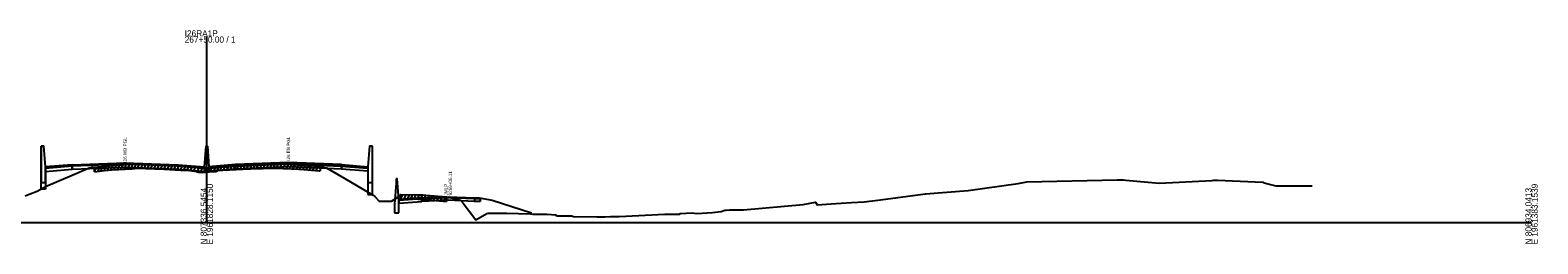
# Model space of a CAD drawing. Extents: x 1017 to 19997, y -1947 to 50737.
# Drawn here: x 10520 to 11203, y 17490 to 17587 of the extents above; entities that cross this region are included whole.
import ezdxf

# ---------------------------------------------------------------- set-up
doc = ezdxf.new("R2010")
doc.units = 0
for name, color, linetype in [('RD_GPK_XS_Cell', 7, 'Continuous'), ('RD_XS_Base', 7, 'Continuous'), ('RD_XS_ExGround', 7, 'Continuous'), ('RD_XS_ExPaveRet', 7, 'Continuous'), ('RD_XS_Greenside', 7, 'Continuous'), ('RD_XS_MedBWall', 7, 'Continuous'), ('RD_XS_Pave', 7, 'Continuous'), ('RD_XS_PaveOvlay', 7, 'Continuous'), ('RD_XS_TX_Notes', 7, 'Continuous')]:
    doc.layers.add(name, color=color, linetype=linetype)

msp = doc.modelspace()

# ---------------------------------------------------------------- linework, layer by layer
at = {"layer": 'RD_GPK_XS_Cell'}
for p, q in [((10600, 17500), (10600, 17584.1)), ((10000, 17500), (10600, 17500)), ((10600, 17500), (11200, 17500))]:
    msp.add_line(p, q, dxfattribs=at)
at = {"layer": 'RD_XS_Base'}
for points in [[(10539, 17525.36), (10527, 17524.4)], [(10527, 17524.4), (10527, 17523.06)], [(10527, 17523.06), (10539, 17524.02)], [(10539, 17524.02), (10539, 17525.36)], [(10539.05, 17524.03), (10539, 17524.02)], [(10539.05, 17525.37), (10539.05, 17524.03)], [(10539.05, 17524.03), (10563, 17525), (10587, 17524.03)], [(10587, 17524.03), (10587, 17525.37)], [(10599, 17524.43), (10587, 17525.37)], [(10587, 17524.03), (10599, 17523.09)], [(10599, 17523.09), (10599, 17524.43)], [(10601, 17523.18), (10601, 17524.52)], [(10613, 17524.12), (10601, 17523.18)], [(10613, 17524.12), (10613, 17525.46)], [(10660.95, 17524.12), (10637, 17525.09), (10613, 17524.12)], [(10660.95, 17524.12), (10660.95, 17525.46)], [(10661, 17524.12), (10660.95, 17524.12)], [(10661, 17525.46), (10661, 17524.12)], [(10661, 17525.45), (10673, 17524.49)], [(10661, 17524.11), (10661, 17525.45)], [(10673, 17523.15), (10661, 17524.11)], [(10673, 17524.49), (10673, 17523.15)], [(10697.32, 17510.84), (10687, 17510.02)], [(10687, 17510.02), (10687, 17508.68)], [(10687, 17508.68), (10697.32, 17509.51)], [(10697.32, 17510.84), (10709.32, 17511.31), (10721.32, 17510.83)], [(10697.32, 17509.51), (10697.32, 17510.84)], [(10721.32, 17509.52), (10709.32, 17509.98), (10697.32, 17509.51)], [(10721.32, 17510.83), (10721.32, 17509.52)], [(10721.32, 17510.83), (10723.32, 17510.75), (10723.82, 17510.73)], [(10723.82, 17509.4), (10721.32, 17509.52)], [(10723.82, 17510.73), (10723.82, 17509.4)]]:
    msp.add_lwpolyline(points, dxfattribs=at)
at = {"layer": 'RD_XS_ExGround'}
msp.add_lwpolyline([(10517.81, 17511.94), (10520.06, 17512.95), (10523.24, 17514.1), (10526.99, 17516.2), (10539.06, 17521.37), (10546.8, 17524.7), (10547.83, 17525.02), (10548.13, 17525.06), (10548.68, 17525.04), (10549.08, 17524.92), (10553.65, 17525.43), (10557.05, 17525.77), (10566.08, 17526.3), (10568.86, 17526.48), (10572.21, 17526.35), (10580.7, 17526.05), (10588.25, 17525.68), (10592.24, 17525.52), (10594.48, 17525.24), (10595.09, 17525.17), (10595.48, 17524.82), (10596.08, 17524.75), (10598.28, 17524.53), (10600.26, 17524.72), (10601.13, 17524.81), (10604.1, 17525.01), (10604.34, 17525.16), (10604.72, 17525.19), (10605, 17525.41), (10607.19, 17525.64), (10619.36, 17526.28), (10620.02, 17526.29), (10631.3, 17526.5), (10641.68, 17526.03), (10643.92, 17525.93), (10650.9, 17525.36), (10651.41, 17525.32), (10652.9, 17525.02), (10654.24, 17524.73), (10660.76, 17520.91), (10675.34, 17512.36), (10676.09, 17511.65), (10678.02, 17509.56), (10679.34, 17509.56), (10680.78, 17509.56), (10682.12, 17509.56), (10683.59, 17509.56), (10686.48, 17511.34), (10687.83, 17512.6), (10695.73, 17512.45), (10697.83, 17512.47), (10699.18, 17512.31), (10708.52, 17511.5), (10713.82, 17510.36), (10714.98, 17510.01), (10716.1, 17508.65), (10721.83, 17501.2), (10726.78, 17504.02), (10727.42, 17504.19), (10735.77, 17504.15), (10746.65, 17503.84), (10747.69, 17503.65), (10753.95, 17503.66), (10758.01, 17503.41), (10758.11, 17503.17), (10758.7, 17502.98), (10765.18, 17502.9), (10766.14, 17502.64), (10776.72, 17502.46), (10780.3, 17502.58), (10782.8, 17502.71), (10786.81, 17502.62), (10807.43, 17503.7), (10814.27, 17503.74), (10814.37, 17503.97), (10814.42, 17503.97), (10819.84, 17504.37), (10821.79, 17504.07), (10829.1, 17504.5), (10832.9, 17504.98), (10834.55, 17505.51), (10835.41, 17505.5), (10836.76, 17505.61), (10843.02, 17505.74), (10870.03, 17508.07), (10875.68, 17509.08), (10876.37, 17507.88), (10882.78, 17508.43), (10887.24, 17508.64), (10892.06, 17509.04), (10897.66, 17509.3), (10903.94, 17509.98), (10925.51, 17512.93), (10944.83, 17514.46), (10967.52, 17517.66), (10971.46, 17518.33), (11012.24, 17519.32), (11013.93, 17519.28), (11014.35, 17519.29), (11015.21, 17519.25), (11016.28, 17519.14), (11031.34, 17517.78), (11055.35, 17519.01), (11055.93, 17519.05), (11056.97, 17519.08), (11057.72, 17519.03), (11078.31, 17518.13), (11078.72, 17517.94), (11084.12, 17516.57), (11090.8, 17516.57), (11096.66, 17516.57), (11100.65, 17516.57)], dxfattribs=at)
at = {"layer": 'RD_XS_ExPaveRet'}
for p, q in [((10549.08, 17522.92), (10550.14, 17525.03)), ((10549.08, 17522.92), (10549.08, 17524.92)), ((10549.08, 17522.92), (10553.65, 17523.43)), ((10550.58, 17523.08), (10551.64, 17525.2)), ((10552.08, 17523.25), (10553.14, 17525.37)), ((10553.58, 17523.42), (10554.63, 17525.53)), ((10553.65, 17523.43), (10557.05, 17523.77)), ((10555.08, 17523.57), (10556.13, 17525.68)), ((10556.58, 17523.72), (10557.62, 17525.8)), ((10557.05, 17523.77), (10566.08, 17524.3)), ((10558.08, 17523.83), (10559.11, 17525.89)), ((10559.58, 17523.92), (10560.61, 17525.98)), ((10561.08, 17524), (10562.11, 17526.06)), ((10562.58, 17524.09), (10563.61, 17526.15)), ((10564.08, 17524.18), (10565.11, 17526.24)), ((10565.58, 17524.27), (10566.61, 17526.33)), ((10566.08, 17524.3), (10568.86, 17524.48)), ((10567.08, 17524.36), (10568.11, 17526.43)), ((10568.58, 17524.46), (10569.57, 17526.45)), ((10568.86, 17524.48), (10572.21, 17524.35)), ((10570.08, 17524.43), (10571.06, 17526.39)), ((10571.58, 17524.37), (10572.56, 17526.34)), ((10572.21, 17524.35), (10580.7, 17524.05)), ((10573.08, 17524.32), (10574.06, 17526.28)), ((10574.58, 17524.27), (10575.56, 17526.23)), ((10576.08, 17524.21), (10577.06, 17526.18)), ((10577.58, 17524.16), (10578.56, 17526.12)), ((10579.08, 17524.11), (10580.06, 17526.07)), ((10580.58, 17524.05), (10581.55, 17526.01)), ((10580.7, 17524.05), (10588.25, 17523.68)), ((10582.08, 17523.98), (10583.05, 17525.94)), ((10583.58, 17523.91), (10584.55, 17525.86)), ((10585.08, 17523.84), (10586.05, 17525.79)), ((10586.58, 17523.77), (10587.55, 17525.72)), ((10588.08, 17523.69), (10589.06, 17525.65)), ((10588.25, 17523.68), (10592.24, 17523.52)), ((10589.58, 17523.63), (10590.56, 17525.59)), ((10591.08, 17523.57), (10592.06, 17525.53)), ((10592.24, 17523.52), (10594.48, 17523.24)), ((10592.58, 17523.48), (10593.52, 17525.36)), ((10594.08, 17523.29), (10595.02, 17525.18)), ((10594.48, 17523.24), (10595.09, 17523.17)), ((10595.09, 17523.17), (10595.48, 17522.82)), ((10595.48, 17522.82), (10596.08, 17522.75)), ((10595.58, 17522.8), (10596.53, 17524.7)), ((10596.08, 17522.75), (10598.28, 17522.53)), ((10597.08, 17522.65), (10598.03, 17524.55)), ((10598.28, 17522.53), (10600.26, 17522.72)), ((10598.58, 17522.56), (10599.63, 17524.66)), ((10600.08, 17522.71), (10601.13, 17524.81)), ((10600.26, 17522.72), (10601.13, 17522.81)), ((10601.13, 17522.81), (10604.1, 17523.01)), ((10601.58, 17522.84), (10602.61, 17524.91)), ((10603.08, 17522.94), (10604.12, 17525.02)), ((10604.1, 17523.01), (10604.34, 17523.16)), ((10604.34, 17523.16), (10604.72, 17523.19)), ((10604.58, 17523.18), (10605.73, 17525.49)), ((10604.72, 17523.19), (10605, 17523.41)), ((10605, 17523.41), (10607.19, 17523.64)), ((10606.08, 17523.52), (10607.13, 17525.63)), ((10607.19, 17523.64), (10619.36, 17524.28)), ((10607.58, 17523.66), (10608.6, 17525.71)), ((10609.08, 17523.74), (10610.1, 17525.79)), ((10610.58, 17523.82), (10611.6, 17525.87)), ((10612.08, 17523.9), (10613.1, 17525.95)), ((10613.58, 17523.98), (10614.6, 17526.03)), ((10615.08, 17524.05), (10616.1, 17526.11)), ((10616.58, 17524.13), (10617.6, 17526.19)), ((10618.08, 17524.21), (10619.1, 17526.27)), ((10619.36, 17524.28), (10620.02, 17524.29)), ((10619.58, 17524.28), (10620.59, 17526.3)), ((10620.02, 17524.29), (10631.3, 17524.5)), ((10621.08, 17524.31), (10622.09, 17526.33)), ((10622.58, 17524.34), (10623.59, 17526.36)), ((10624.08, 17524.37), (10625.09, 17526.39)), ((10625.58, 17524.4), (10626.59, 17526.42)), ((10627.08, 17524.43), (10628.09, 17526.44)), ((10628.58, 17524.45), (10629.59, 17526.47)), ((10630.08, 17524.48), (10631.09, 17526.5)), ((10631.3, 17524.5), (10641.68, 17524.03)), ((10631.58, 17524.49), (10632.55, 17526.45)), ((10633.08, 17524.42), (10634.05, 17526.38)), ((10634.58, 17524.36), (10635.55, 17526.31)), ((10636.08, 17524.29), (10637.05, 17526.24)), ((10637.58, 17524.22), (10638.55, 17526.17)), ((10639.08, 17524.15), (10640.05, 17526.11)), ((10640.58, 17524.08), (10641.55, 17526.04)), ((10641.68, 17524.03), (10643.92, 17523.93)), ((10642.08, 17524.01), (10643.05, 17525.97)), ((10643.58, 17523.94), (10644.54, 17525.88)), ((10643.92, 17523.93), (10650.9, 17523.36)), ((10645.08, 17523.83), (10646.04, 17525.76)), ((10646.58, 17523.71), (10647.54, 17525.63)), ((10648.08, 17523.59), (10649.04, 17525.51)), ((10649.58, 17523.47), (10650.54, 17525.39)), ((10650.9, 17523.36), (10651.41, 17523.32)), ((10651.41, 17525.32), (10651.41, 17523.32)), ((10687.83, 17510.6), (10687.83, 17512.6)), ((10687.83, 17510.6), (10688.82, 17512.58)), ((10687.83, 17510.6), (10695.73, 17510.45)), ((10689.33, 17510.57), (10690.32, 17512.55)), ((10690.83, 17510.54), (10691.82, 17512.52)), ((10692.33, 17510.51), (10693.32, 17512.5)), ((10693.83, 17510.49), (10694.82, 17512.47)), ((10695.33, 17510.46), (10696.33, 17512.46)), ((10695.73, 17510.45), (10697.83, 17510.47)), ((10696.83, 17510.46), (10697.84, 17512.47)), ((10697.83, 17510.47), (10699.18, 17510.31)), ((10698.33, 17510.41), (10699.28, 17512.31)), ((10699.18, 17510.31), (10708.52, 17509.5)), ((10699.83, 17510.26), (10700.79, 17512.18)), ((10701.33, 17510.13), (10702.29, 17512.05)), ((10702.83, 17510), (10703.79, 17511.92)), ((10704.33, 17509.87), (10705.29, 17511.79)), ((10705.83, 17509.74), (10706.79, 17511.65)), ((10707.33, 17509.61), (10708.29, 17511.52)), ((10708.52, 17511.5), (10708.52, 17509.5))]:
    msp.add_line(p, q, dxfattribs=at)
at = {"layer": 'RD_XS_Greenside'}
for points in [[(10723.32, 17511.07), (10729.32, 17510.11)], [(10729.32, 17510.11), (10747.06, 17504.26)]]:
    msp.add_lwpolyline(points, dxfattribs=at)
at = {"layer": 'RD_XS_MedBWall'}
for points in [[(10527, 17525.08), (10526.25, 17534.42), (10525, 17534.42)], [(10525, 17534.42), (10525, 17518)], [(10525, 17515.09), (10525, 17534.42)], [(10599, 17525.08), (10599.75, 17534.51), (10600.25, 17534.51), (10601, 17525.17)], [(10675, 17534.51), (10673.75, 17534.51), (10673, 17525.17)], [(10675, 17518), (10675, 17534.51)], [(10675, 17512.56), (10675, 17534.51)], [(10527, 17518), (10527, 17525.08)], [(10527, 17525.08), (10527, 17515.09)], [(10599, 17523.08), (10599, 17525.08)], [(10601, 17523.08), (10599, 17523.08)], [(10601, 17525.17), (10601, 17523.08)], [(10673, 17525.17), (10673, 17518)], [(10673, 17525.17), (10673, 17512.56)], [(10525, 17518), (10527, 17518)], [(10527, 17515.09), (10525, 17515.09)], [(10673, 17518), (10675, 17518)], [(10685.75, 17517.67), (10685, 17508.33)], [(10687, 17510.33), (10686.25, 17519.67), (10685.75, 17519.67)], [(10685.75, 17519.67), (10685.75, 17517.67)], [(10673, 17512.56), (10675, 17512.56)], [(10685, 17508.33), (10685, 17504.33)], [(10687, 17504.33), (10687, 17510.33)], [(10685, 17504.33), (10687, 17504.33)]]:
    msp.add_lwpolyline(points, dxfattribs=at)
at = {"layer": 'RD_XS_Pave'}
for points in [[(10539, 17525.7), (10527, 17524.74)], [(10527, 17524.74), (10527, 17524.4)], [(10539, 17525.36), (10539, 17525.7)], [(10539.05, 17525.37), (10539, 17525.36)], [(10539.05, 17525.71), (10563, 17526.67), (10587, 17525.71)], [(10587, 17525.37), (10563, 17526.34), (10539.05, 17525.37)], [(10539.05, 17525.37), (10539.05, 17525.71)], [(10587, 17525.71), (10587, 17525.37)], [(10587, 17525.71), (10599, 17524.77)], [(10599, 17524.77), (10599, 17524.43)], [(10613, 17525.8), (10601, 17524.86)], [(10601, 17524.52), (10613, 17525.46)], [(10601, 17524.86), (10601, 17524.52)], [(10660.95, 17525.8), (10637, 17526.76), (10613, 17525.8)], [(10613, 17525.46), (10637, 17526.43), (10660.95, 17525.46)], [(10613, 17525.8), (10613, 17525.46)], [(10660.95, 17525.46), (10660.95, 17525.8)], [(10660.95, 17525.8), (10661, 17525.8)], [(10661, 17525.46), (10660.95, 17525.46)], [(10661, 17525.8), (10661, 17525.46)], [(10661, 17525.45), (10661, 17525.79)], [(10673, 17524.83), (10673, 17524.49)]]:
    msp.add_lwpolyline(points, dxfattribs=at)
at = {"layer": 'RD_XS_PaveOvlay'}
for points in [[(10539, 17526.04), (10527, 17525.08)], [(10527, 17525.08), (10527, 17524.74)], [(10539.05, 17526.05), (10539, 17526.04)], [(10539, 17526.04), (10539, 17525.7)], [(10539, 17525.7), (10539.05, 17525.71)], [(10539.05, 17526.05), (10563, 17527), (10587, 17526.04)], [(10539.05, 17525.71), (10539.05, 17526.05)], [(10587, 17526.04), (10587, 17525.71)], [(10587, 17526.04), (10599, 17525.08)], [(10599, 17525.08), (10599, 17524.77)], [(10613, 17526.13), (10601, 17525.17)], [(10601, 17525.17), (10601, 17524.86)], [(10660.95, 17526.14), (10637, 17527.09), (10613, 17526.13)], [(10613, 17526.13), (10613, 17525.8)], [(10660.95, 17525.8), (10660.95, 17526.14)], [(10660.95, 17526.14), (10661, 17526.13)], [(10661, 17526.13), (10661, 17525.8)], [(10661, 17526.13), (10673, 17525.17)], [(10661, 17525.79), (10661, 17526.13)], [(10673, 17524.83), (10661, 17525.79)], [(10673, 17525.17), (10673, 17524.83)], [(10697.32, 17511.16), (10687, 17510.33)], [(10687, 17510.02), (10697.32, 17510.84)], [(10687, 17510.33), (10687, 17510.02)], [(10697.32, 17511.16), (10709.32, 17511.63), (10721.32, 17511.15)], [(10721.32, 17510.83), (10709.32, 17511.31), (10697.32, 17510.84)], [(10697.32, 17510.84), (10697.32, 17511.16)], [(10721.32, 17511.15), (10721.32, 17510.83)], [(10721.32, 17511.15), (10723.32, 17511.07)], [(10723.32, 17510.75), (10721.32, 17510.83)], [(10723.32, 17511.07), (10723.32, 17510.75)]]:
    msp.add_lwpolyline(points, dxfattribs=at)

# ---------------------------------------------------------------- texts
at = {"layer": 'RD_GPK_XS_Cell'}
for s, p in [('267+50.00 / 1', (10590, 17581.3)), ('I26RA1P', (10590, 17584.1))]:
    msp.add_text(s, height=2.8, dxfattribs=at).set_placement(p)
for s, p in [('N 807336.5454', (10600, 17490)), ('E 1961828.1150', (10602.8, 17490)), ('N 806934.0413', (11200, 17490)), ('E 1961383.1539', (11202.8, 17490))]:
    msp.add_text(s, height=2.8, rotation=90, dxfattribs=at).set_placement(p)
at = {"layer": 'RD_XS_TX_Notes'}
for s, p in [('I26 WB PGL', (10563.75, 17527)), ('I26 EB PGL', (10637.75, 17527.83)), (' 9269+06.11', (10711.04, 17511.6)), (' JMLP', (10709.09, 17511.6))]:
    msp.add_text(s, height=1.5, rotation=90, dxfattribs=at).set_placement(p)

doc.saveas('drawing.dxf')
